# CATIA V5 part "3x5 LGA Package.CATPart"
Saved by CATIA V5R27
Part number: 3x5 LGA Package
Definition: 3x5 LGA Package
Nomenclature: 3x5 LGA Package v5
Source: Unknown
Bounding box of the stored display mesh (mm): x 0 to 3, y 0 to 1, z 0 to 5
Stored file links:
  E:\university\my-thesis\My Thesis Publication\Final-Updata\CAD\3x5 LGA Package.CATPart
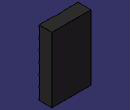
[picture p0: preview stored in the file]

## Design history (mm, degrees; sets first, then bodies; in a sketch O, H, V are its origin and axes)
Body1 "Body1" (main body)
  Solid1: solid without history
